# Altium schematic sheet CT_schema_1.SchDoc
size 603 x 258 mm
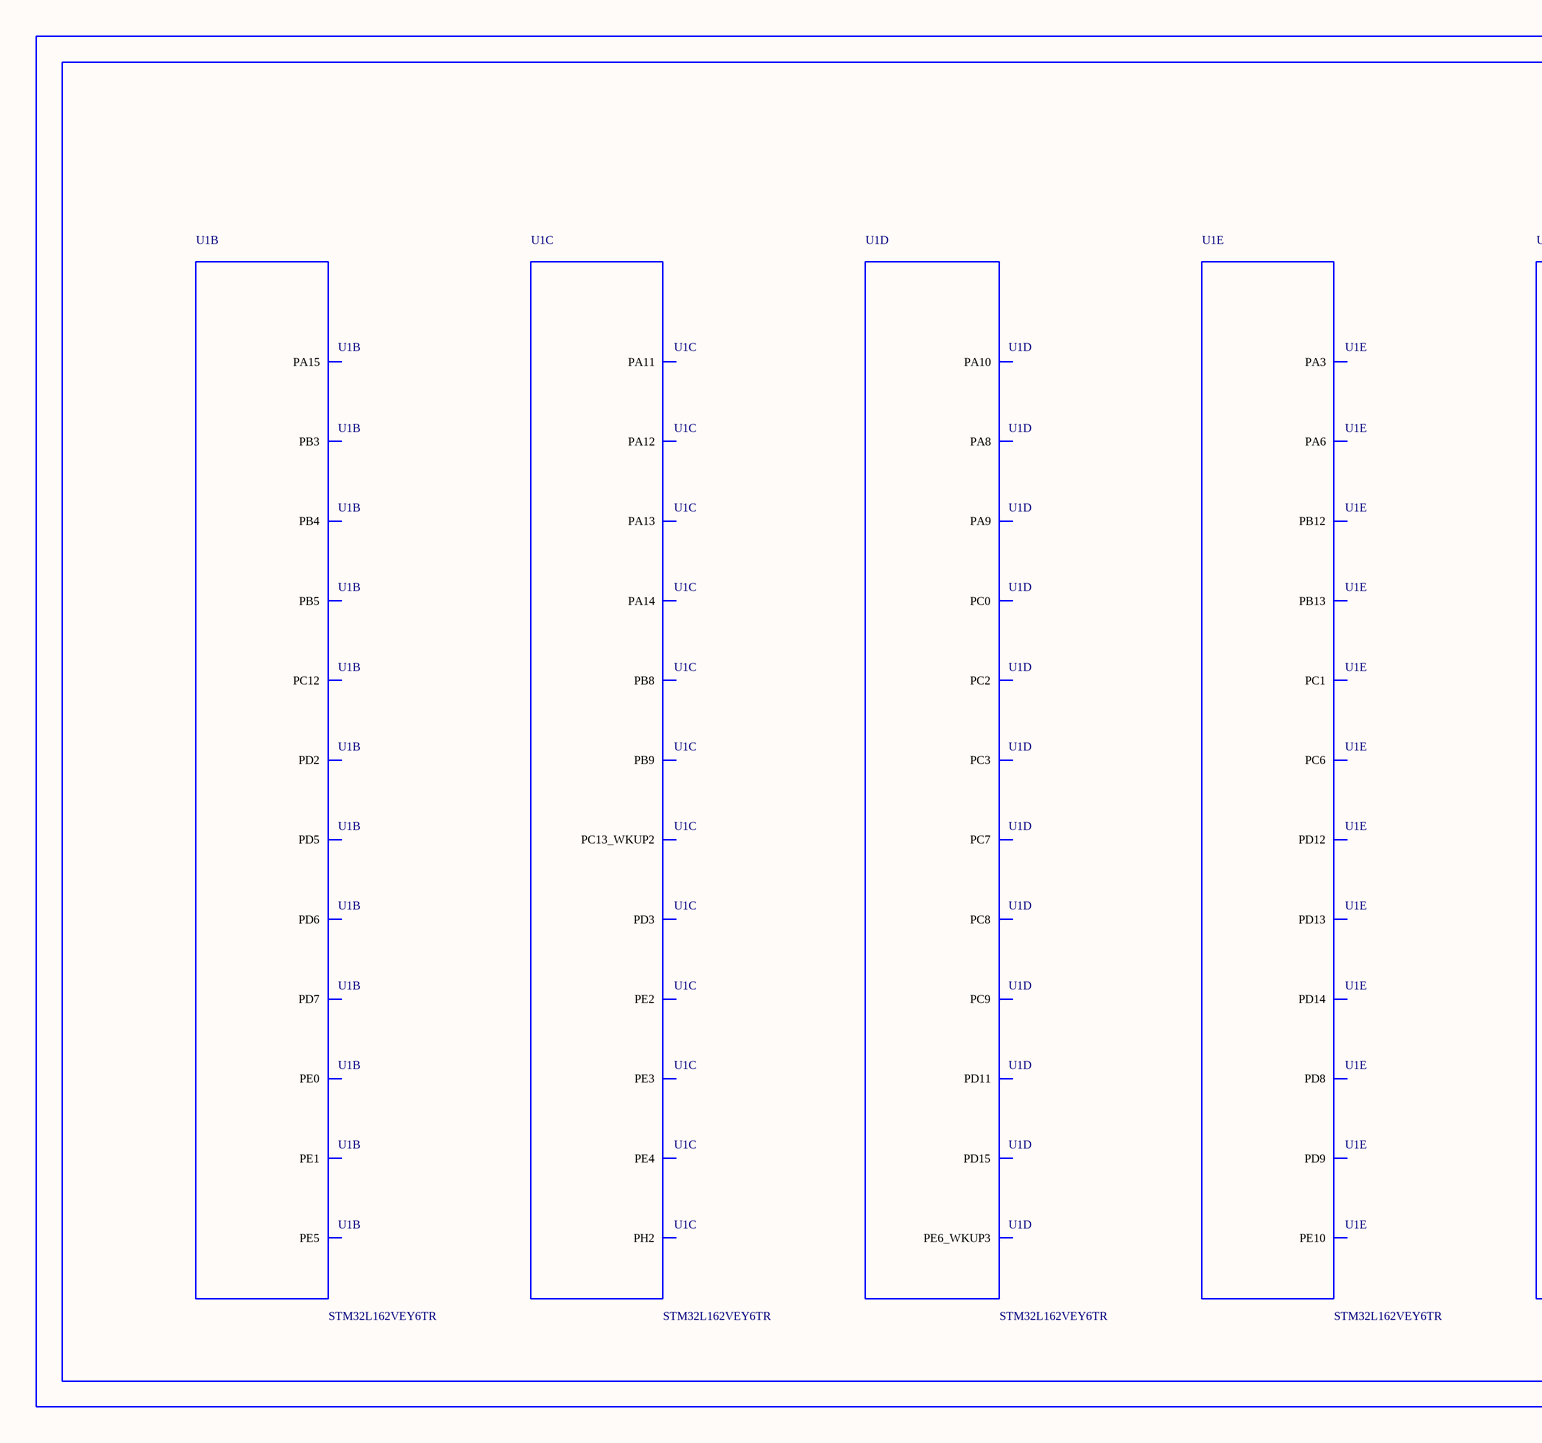
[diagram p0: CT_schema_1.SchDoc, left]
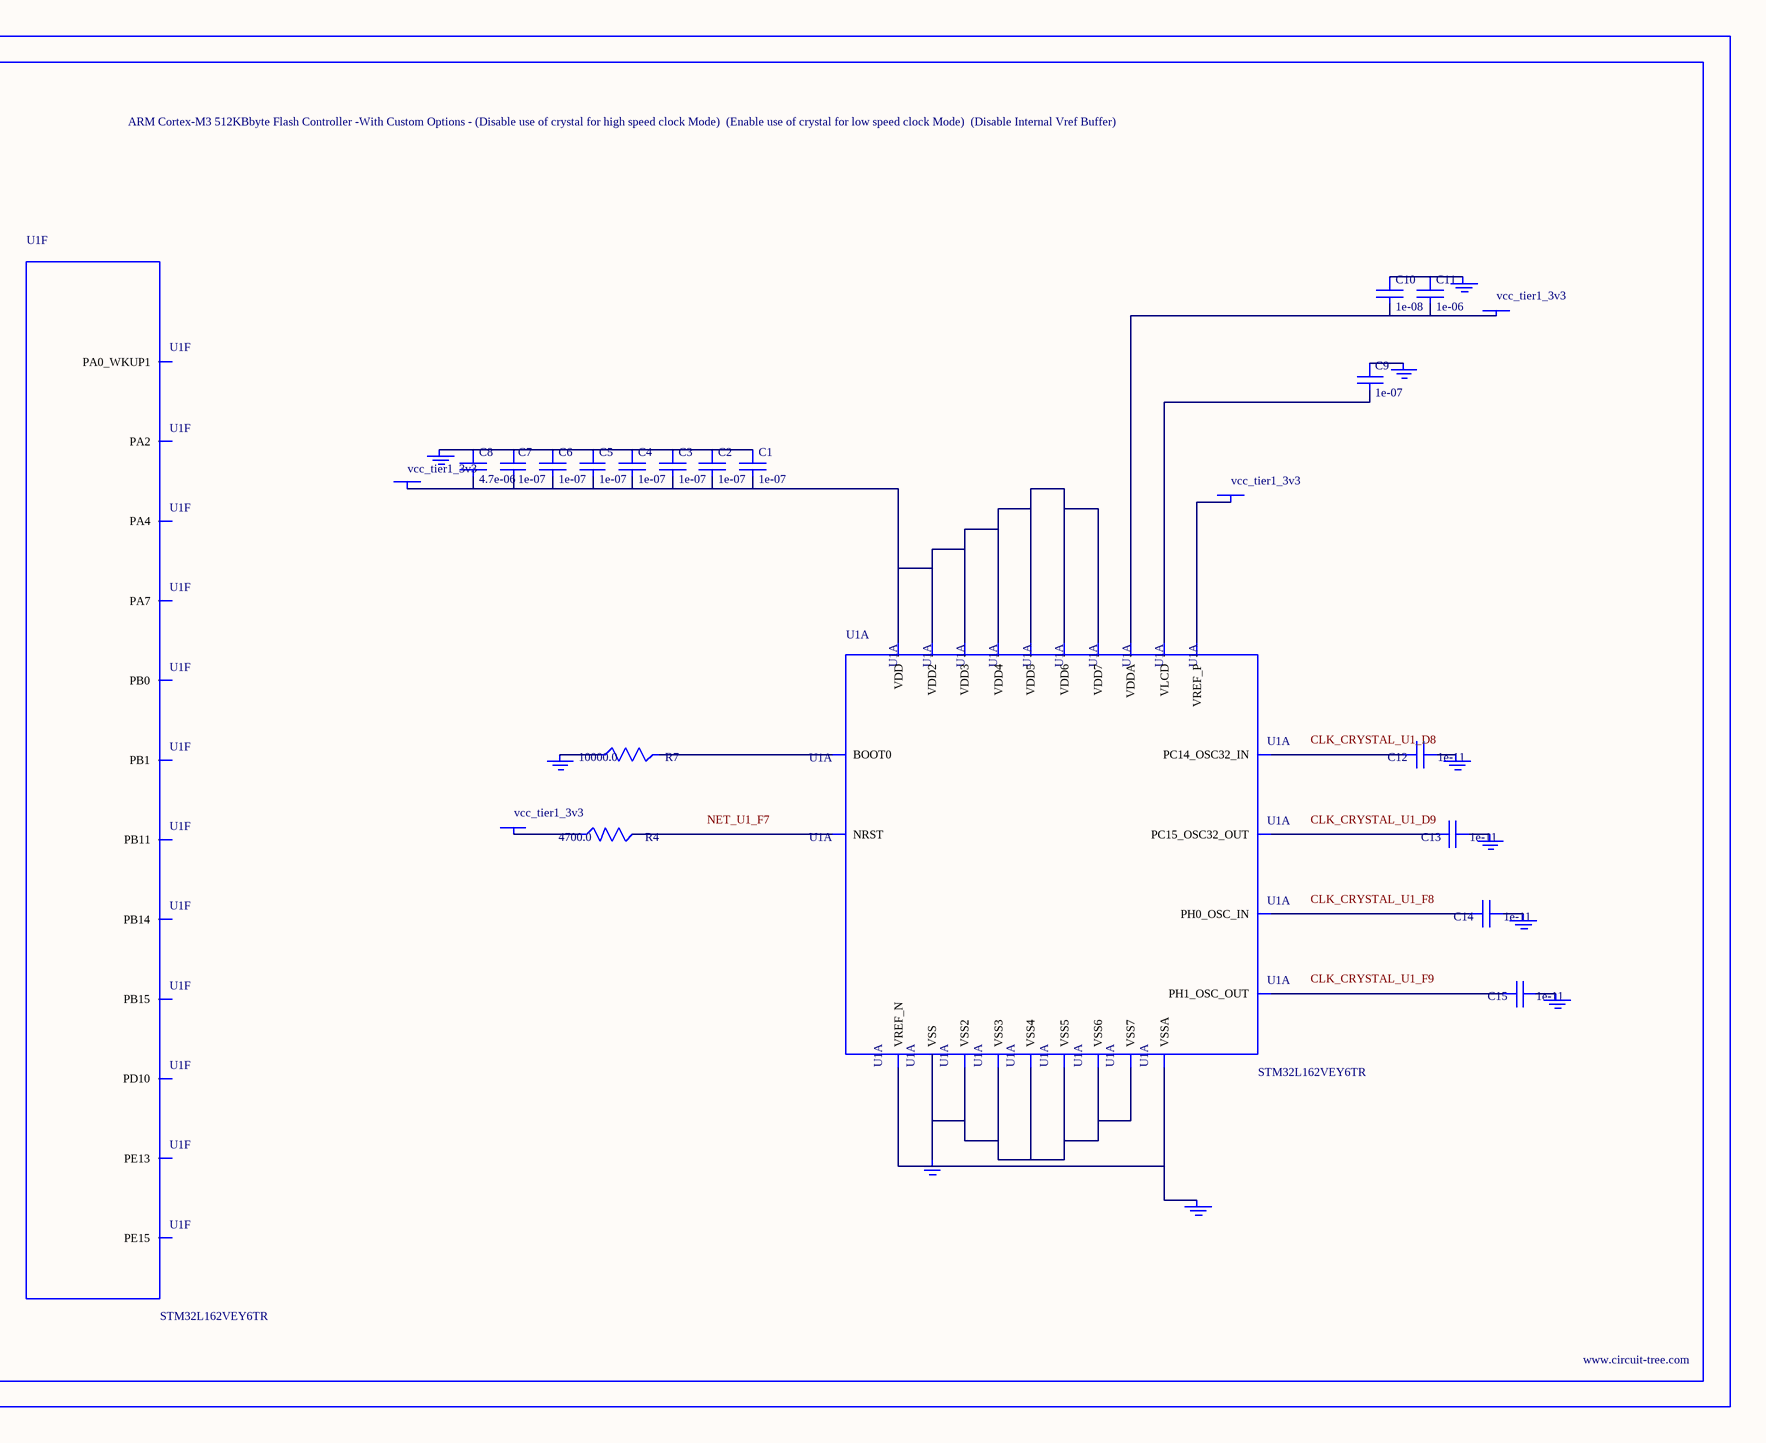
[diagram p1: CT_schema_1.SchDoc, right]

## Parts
BORDER0  (no value)
C1  1e-07  [C0603]
C2  1e-07  [C0603]
C3  1e-07  [C0603]
C4  1e-07  [C0603]
C5  1e-07  [C0603]
C6  1e-07  [C0603]
C7  1e-07  [C0603]
C8  4.7e-06  [C0603]
C9  1e-07  [C0603]
C10  1e-08  [C0603]
C11  1e-06  [C0603]
C12  1e-11  [C0402]
C13  1e-11  [C0402]
C14  1e-11  [C0402]
C15  1e-11  [C0402]
GND_INSTANCE_0_0  (no value)
GND_INSTANCE_0_1  (no value)
GND_INSTANCE_0_2  (no value)
GND_INSTANCE_0_3  (no value)
GND_INSTANCE_0_4  (no value)
GND_INSTANCE_0_5  (no value)
GND_INSTANCE_0_6  (no value)
GND_INSTANCE_0_7  (no value)
GND_INSTANCE_0_8  (no value)
GND_INSTANCE_0_9  (no value)
POWER_INSTANCE_0_0  vcc_tier1_3v3
POWER_INSTANCE_0_1  vcc_tier1_3v3
POWER_INSTANCE_0_2  vcc_tier1_3v3
POWER_INSTANCE_0_3  vcc_tier1_3v3
R4  4700.0  [R0603]
R7  10000.0  [R0603]
U1  STM32L162VEY6TR  [WLCSP104]  (parts A,B,C,D,E,F of 9)

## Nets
NetC1_1: C1.1 C2.1 C3.1 C4.1 C5.1 C6.1 C7.1 C8.1 GND_INSTANCE_0_0.0(GND)
NetC1_2: C1.2 C2.2 C3.2 C4.2 C5.2 C6.2 C7.2 C8.2 POWER_INSTANCE_0_0.0(PWR) U1.A9(VDD) U1.B8(VDD2) U1.C1(VDD3) U1.E9(VDD4) U1.K3(VDD5) U1.L8(VDD6) U1.M9(VDD7)
NetC9_1: C9.1 GND_INSTANCE_0_1.0(GND)
NetC9_2: C9.2 U1.E7(VLCD)
NetC10_1: C10.1 C11.1 GND_INSTANCE_0_3.0(GND)
NetC10_2: C10.2 C11.2 POWER_INSTANCE_0_1.0(PWR) U1.G6(VDDA)
NetC12_1: C12.1 GND_INSTANCE_0_4.0(GND)
NetC12_2: C12.2 U1.D8(PC14_OSC32_IN)
NetC13_1: C13.1 GND_INSTANCE_0_5.0(GND)
NetC13_2: C13.2 U1.D9(PC15_OSC32_OUT)
NetC14_1: C14.1 GND_INSTANCE_0_6.0(GND)
NetC14_2: C14.2 U1.F8(PH0_OSC_IN)
NetC15_1: C15.1 GND_INSTANCE_0_7.0(GND)
NetC15_2: C15.2 U1.F9(PH1_OSC_OUT)
NetGND_INSTANCE_0_2_0: GND_INSTANCE_0_2.0(GND) R7.1
NetGND_INSTANCE_0_8_0: GND_INSTANCE_0_8.0(GND) U1.H8(VREF_N) U1.J9(VSSA)
NetGND_INSTANCE_0_9_0: GND_INSTANCE_0_9.0(GND) U1.A1(VSS) U1.C7(VSS2) U1.D2(VSS3) U1.E8(VSS4) U1.K8(VSS5) U1.L2(VSS6) U1.M1(VSS7)
NetPOWER_INSTANCE_0_2_0: POWER_INSTANCE_0_2.0(PWR) U1.G7(VREF_P)
NetPOWER_INSTANCE_0_3_0: POWER_INSTANCE_0_3.0(PWR) R4.1
NetR4_2: R4.2 U1.F7(NRST)
NetR7_2: R7.2 U1.A7(BOOT0)

Not connected (* = marked no-connect by the designer): U1 A4(PD7) A5(PB4) A6(PB5) A8(PE1) B1(PA15) B2(PC12) B3(PD5) B4(PD6) B5(PB3) B7(PE0) B9(PE5) C3(PD2) C4(PD3) C6(PB9) C8(PE4) C9(PC13_WKUP2) D1(PH2) D3(PA14) D5(PB8) D6(PE2) D7(PE3) E1(PA11) E2(PA12) E3(PA13) E6(PE6_WKUP3) F1(PA9) F2(PA10) F3(PA8) F4(PC9) F6(PC0) G1(PC7) G2(PC8) G3(PD15) G4(PD11) G8(PC3) G9(PC2) H1(PC6) H2(PD13) H3(PD12) H4(PD8) H6(PA6) H7(PA3) H9(PC1) J1(PD14) J2(PD9) J3(PB13) J4(PB12) J5(PE10) J6(PB0) J7(PA4) J8(PA2) K1(PD10) K2(PB15) K4(PE15) K5(PE13) K6(PB1) K7(PA7) K9(PA0_WKUP1) L1(PB14) L3(PB11)

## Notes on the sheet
- Labels drawn without touching a wire or pin: CLK_CRYSTAL_U1_D8, CLK_CRYSTAL_U1_D9, CLK_CRYSTAL_U1_F8, CLK_CRYSTAL_U1_F9, NET_U1_F7

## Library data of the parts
BORDER0 = BORDER_PAGE0
C1-C7 C9 = 06035C104K4Z2A
C8 = GRM188R6YA475KE15D
C10 = 06035C103K4Z2A
C11 = C0603C105K3RACTU
C12-C15 = C0402C100K3GACTU
GND_INSTANCE_0_0-GND_INSTANCE_0_9 = GND
POWER_INSTANCE_0_0-POWER_INSTANCE_0_3 = PWR
R4 = RC0603JR-074K7L
R7 = RC0603JR-0710KL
